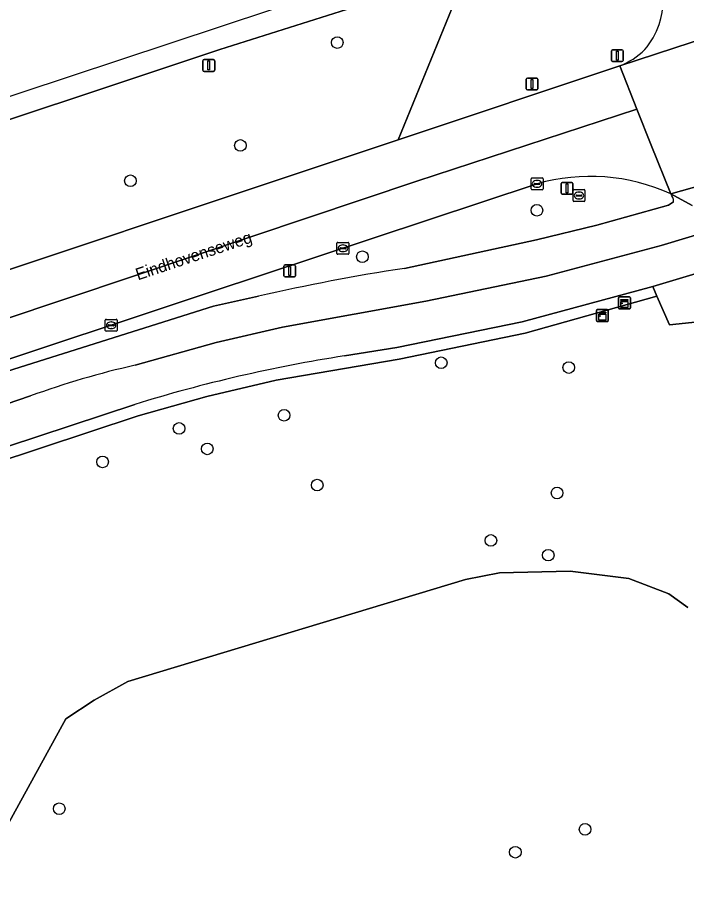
# Model space of a CAD drawing. Extents: x 162082 to 163401, y 388089 to 388636.
# Drawn here: x 162135.7 to 162191.9, y 388429.5 to 388502.7 of the extents above; entities that cross this region are included whole.
import ezdxf

# ---------------------------------------------------------------- set-up
doc = ezdxf.new("R2010")
doc.units = 0
for name, color, linetype in [('IMGEO_Berm_groen', 7, 'Continuous'), ('IMGEO_Boom', 7, 'Continuous'), ('IMGEO_Fietspad_gesloten', 7, 'Continuous'), ('IMGEO_Groenvoorziening', 7, 'Continuous'), ('IMGEO_Kast', 7, 'Continuous'), ('IMGEO_Kolk', 7, 'Continuous'), ('IMGEO_Lichtmast', 7, 'Continuous'), ('IMGEO_Loofbos', 7, 'Continuous'), ('IMGEO_Openbare_ruimte_label', 7, 'Continuous'), ('IMGEO_Rijbaan_regionaal_gesloten', 7, 'Continuous'), ('IMGEO_Rioolput', 7, 'Continuous'), ('IMGEO_Verkeersbordpaal', 7, 'Continuous'), ('IMGEO_Verkeersregelinstallatiepaal', 7, 'Continuous'), ('IMGEO_Voetpad_open', 7, 'Continuous')]:
    doc.layers.add(name, color=color, linetype=linetype)

msp = doc.modelspace()

# ---------------------------------------------------------------- linework, layer by layer
at = {"layer": 'IMGEO_Berm_groen'}
for points in [[(162182.913, 388509.596), (162173.435, 388506.586), (162172.94, 388505.371), (162168.161, 388493.65), (162167.664, 388492.43), (162186.253, 388498.633)], [(162179.321, 388488.723), (162151.79, 388479.601), (162130.844, 388472.616), (162126.677, 388471.258), (162126.927, 388470.499), (162126.415, 388470.328), (162152.169, 388478.453)], [(162145.551, 388470.202), (162124.066, 388463.101), (162124.127, 388462.752), (162115.246, 388459.072), (162115.132, 388459.761), (162115.076, 388460.073), (162114.525, 388463.169), (162114.5, 388463.309), (162113.845, 388466.99), (162112.598, 388473.997), (162112.45, 388474.83), (162112.381, 388475.216), (162110.598, 388485.039), (162110.577, 388485.155), (162110.422, 388486.009), (162110.1, 388487.783), (162106.061, 388486.443), (162106.271, 388485.258), (162104.283, 388484.864), (162104.113, 388485.797)], [(162168.184, 388481.623), (162179.283, 388484.025), (162184.324, 388485.241), (162190.345, 388486.937), (162190.774, 388487.218)], [(162220.353, 388411.769), (162198.713, 388479.081), (162197.9, 388480.945), (162196.87, 388482.458), (162189.034, 388480.096), (162189.38, 388479.302), (162190.438, 388476.87), (162194.958, 388477.348), (162199.885, 388462.478), (162209.231, 388435.377), (162217.14, 388410.656)], [(162129.502, 388463.844), (162145.851, 388469.248), (162151.603, 388470.876), (162157.431, 388472.224), (162167.732, 388473.998), (162178.317, 388476.172), (162189.38, 388479.302), (162189.034, 388480.096), (162178.08, 388477.144), (162167.552, 388474.982), (162163.164, 388474.276)], [(162152.169, 388478.453), (162155.945, 388479.29)]]:
    msp.add_lwpolyline(points, dxfattribs=at)
msp.add_lwpolyline([(162168.161, 388493.65), (162172.94, 388505.371), (162173.435, 388506.586), (162152.7, 388500), (162125.209, 388490.852), (162119.403, 388488.96), (162119.574, 388488.142), (162119.595, 388488.041), (162121.418, 388478.225), (162121.508, 388477.815), (162121.67, 388477.082), (162167.664, 388492.43)], close=True, dxfattribs=at)
for centre, radius, start, end in [((162183.61, 388504.121), 6.28, 341.22895, 18.96852), ((162183.477, 388504.169), 6.421, 319.51382, 341.2023), ((162184.088, 388504.281), 6.049, 290.97595, 314.94941), ((162183.786, 388473.192), 16.16, 65.31255, 106.03852), ((162189.743, 388487.215), 1.031, 0.17871, 39.8015), ((162193.777, 388314.091), 169.476, 98.68567, 102.89884), ((162182.258, 388351.619), 124.134, 98.84807, 107.1996)]:
    msp.add_arc(centre, radius, start, end, dxfattribs=at)
at = {"layer": 'IMGEO_Boom'}
for centre in [(162162.551, 388500.587), (162154.419, 388491.944), (162145.193, 388488.979), (162179.305, 388486.503), (162164.658, 388482.601), (162171.272, 388473.696), (162181.977, 388473.297), (162158.087, 388469.288), (162149.277, 388468.179), (162151.642, 388466.468), (162142.852, 388465.373), (162160.866, 388463.424), (162180.994, 388462.764), (162175.439, 388458.777), (162180.254, 388457.541), (162139.216, 388436.249), (162183.344, 388434.516), (162177.494, 388432.599)]:
    msp.add_circle(centre, 0.489, dxfattribs=at)
at = {"layer": 'IMGEO_Fietspad_gesloten'}
for points in [[(162192.329, 388486.909), (162190.535, 388487.875)], [(162190.774, 388487.218), (162190.345, 388486.937), (162184.324, 388485.241), (162179.283, 388484.025), (162168.184, 388481.623)], [(162169.99, 388478.857), (162180.07, 388480.967), (162189.741, 388483.554), (162194.648, 388485.031)], [(162155.945, 388479.29), (162152.169, 388478.453), (162126.415, 388470.328), (162125.474, 388470.031), (162122.99, 388469.247), (162123.493, 388466.375), (162123.631, 388466.422), (162136.803, 388470.914)], [(162145.584, 388473.491), (162152.396, 388475.404), (162157.94, 388476.675), (162169.99, 388478.857)]]:
    msp.add_lwpolyline(points, dxfattribs=at)
for centre, radius, start, end in [((162189.743, 388487.215), 1.031, 0.17871, 39.8015), ((162193.777, 388314.091), 169.476, 98.68567, 102.89884), ((162161.295, 388403.708), 71.529, 102.68796, 110.02328)]:
    msp.add_arc(centre, radius, start, end, dxfattribs=at)
at = {"layer": 'IMGEO_Groenvoorziening'}
msp.add_lwpolyline([(162191.968, 388453.155), (162190.366, 388454.283), (162187.024, 388455.572), (162182.083, 388456.211), (162176.166, 388456.047), (162173.323, 388455.508), (162144.984, 388446.93), (162142.155, 388445.363), (162139.758, 388443.795), (162134.886, 388434.881), (162134.756, 388429.774), (162130.402, 388429.182)], dxfattribs=at)
at = {"layer": 'IMGEO_Kast'}
for p, q in [((162186.15, 388478.297), (162186.15, 388479.138)), ((162186.15, 388479.138), (162186.15, 388478.297)), ((162186.225, 388479.222), (162187.066, 388479.222)), ((162187.066, 388479.222), (162186.225, 388479.222)), ((162187.15, 388479.147), (162187.15, 388478.306)), ((162187.15, 388478.306), (162187.15, 388479.147)), ((162187.075, 388478.222), (162186.234, 388478.222)), ((162186.234, 388478.222), (162187.075, 388478.222)), ((162184.297, 388477.235), (162184.297, 388478.076)), ((162184.297, 388478.076), (162184.297, 388477.235)), ((162184.372, 388478.16), (162185.213, 388478.16)), ((162185.213, 388478.16), (162184.372, 388478.16)), ((162185.297, 388478.085), (162185.297, 388477.244)), ((162185.297, 388477.244), (162185.297, 388478.085)), ((162185.222, 388477.16), (162184.381, 388477.16)), ((162184.381, 388477.16), (162185.222, 388477.16))]:
    msp.add_line(p, q, dxfattribs=at)
for points in [[(162186.345, 388479.012), (162186.945, 388479.012), (162186.945, 388478.927), (162186.345, 388478.927), (162186.345, 388479.012)], [(162186.345, 388478.837), (162186.945, 388478.837), (162186.945, 388478.348), (162186.345, 388478.348), (162186.345, 388478.837)], [(162184.492, 388477.95), (162185.092, 388477.95), (162185.092, 388477.865), (162184.492, 388477.865), (162184.492, 388477.95)], [(162184.492, 388477.775), (162185.092, 388477.775), (162185.092, 388477.286), (162184.492, 388477.286), (162184.492, 388477.775)]]:
    msp.add_lwpolyline(points, dxfattribs=at)
for centre in [(162186.429, 388478.686), (162184.576, 388477.624)]:
    msp.add_circle(centre, 0.0377, dxfattribs=at)
for centre, start, end in [((162186.228, 388479.144), 92.4484, 184.28452), ((162186.228, 388479.144), 92.4484, 184.28452), ((162187.072, 388479.144), 2.4484, 94.28452), ((162187.072, 388479.144), 2.4484, 94.28452), ((162186.228, 388478.3), 182.4484, 274.28452), ((162186.228, 388478.3), 182.4484, 274.28452), ((162187.072, 388478.3), 272.4484, 4.28452), ((162187.072, 388478.3), 272.4484, 4.28452), ((162184.375, 388478.082), 92.4484, 184.28452), ((162184.375, 388478.082), 92.4484, 184.28452), ((162185.219, 388478.082), 2.4484, 94.28452), ((162185.219, 388478.082), 2.4484, 94.28452), ((162184.375, 388477.238), 182.4484, 274.28452), ((162184.375, 388477.238), 182.4484, 274.28452), ((162185.219, 388477.238), 272.4484, 4.28452), ((162185.219, 388477.238), 272.4484, 4.28452)]:
    msp.add_arc(centre, 0.0779, start, end, dxfattribs=at)
at = {"layer": 'IMGEO_Kolk'}
for p, q in [((162178.892, 388489.221), (162179.744, 388489.221)), ((162178.817, 388488.295), (162178.817, 388489.147)), ((162179.076, 388488.715), (162179.076, 388488.727)), ((162179.514, 388488.678), (162179.116, 388488.678)), ((162179.119, 388488.764), (162179.517, 388488.764)), ((162179.328, 388488.441), (162179.303, 388488.441)), ((162179.305, 388489.001), (162179.33, 388489.001)), ((162179.56, 388488.727), (162179.56, 388488.715)), ((162179.818, 388489.147), (162179.818, 388488.295)), ((162179.744, 388488.221), (162178.892, 388488.221)), ((162162.524, 388482.883), (162162.524, 388483.735)), ((162162.599, 388483.809), (162163.451, 388483.809)), ((162162.783, 388483.303), (162162.783, 388483.315)), ((162162.826, 388483.352), (162163.224, 388483.352)), ((162163.012, 388483.589), (162163.037, 388483.589)), ((162163.267, 388483.315), (162163.267, 388483.303)), ((162163.525, 388483.735), (162163.525, 388482.883)), ((162163.451, 388482.809), (162162.599, 388482.809)), ((162163.221, 388483.266), (162162.823, 388483.266)), ((162163.035, 388483.029), (162163.01, 388483.029)), ((162143.078, 388476.419), (162143.078, 388477.271)), ((162143.153, 388477.345), (162144.005, 388477.345)), ((162143.337, 388476.839), (162143.337, 388476.851)), ((162143.775, 388476.802), (162143.377, 388476.802)), ((162143.38, 388476.888), (162143.778, 388476.888)), ((162143.566, 388477.125), (162143.591, 388477.125)), ((162143.821, 388476.851), (162143.821, 388476.839)), ((162144.079, 388477.271), (162144.079, 388476.419)), ((162144.005, 388476.345), (162143.153, 388476.345)), ((162143.589, 388476.565), (162143.564, 388476.565))]:
    msp.add_line(p, q, dxfattribs=at)
for points in [[(162178.892, 388489.221), (162179.744, 388489.221)], [(162178.817, 388488.295), (162178.817, 388489.147)], [(162179.818, 388489.147), (162179.818, 388488.295)], [(162179.744, 388488.221), (162178.892, 388488.221)], [(162162.524, 388482.883), (162162.524, 388483.735)], [(162162.599, 388483.809), (162163.451, 388483.809)], [(162163.525, 388483.735), (162163.525, 388482.883)], [(162163.451, 388482.809), (162162.599, 388482.809)], [(162143.078, 388476.419), (162143.078, 388477.271)], [(162143.153, 388477.345), (162144.005, 388477.345)], [(162144.079, 388477.271), (162144.079, 388476.419)], [(162144.005, 388476.345), (162143.153, 388476.345)]]:
    msp.add_lwpolyline(points, dxfattribs=at)
for centre, radius, start, end in [((162178.894, 388489.145), 0.0765, 91.55205, 178.44795), ((162178.894, 388489.145), 0.0765, 91.55205, 178.44795), ((162179.742, 388489.145), 0.0765, 1.55205, 88.44795), ((162179.742, 388489.145), 0.0765, 1.55205, 88.44795), ((162179.116, 388488.724), 0.0403, 85.87752, 175.75265), ((162179.113, 388488.714), 0.0366, 178.93798, 274.71019), ((162179.517, 388488.721), 0.043, 264.86636, 352.45326), ((162179.521, 388488.726), 0.0386, 1.73085, 96.63898), ((162178.894, 388488.297), 0.0765, 181.55205, 268.44795), ((162178.894, 388488.297), 0.0765, 181.55205, 268.44795), ((162179.742, 388488.297), 0.0765, 271.55205, 358.44795), ((162179.742, 388488.297), 0.0765, 271.55205, 358.44795), ((162162.601, 388483.733), 0.0765, 91.55205, 178.44795), ((162162.601, 388483.733), 0.0765, 91.55205, 178.44795), ((162162.823, 388483.312), 0.0403, 85.87752, 175.75265), ((162163.228, 388483.314), 0.0386, 1.73085, 96.63898), ((162163.449, 388483.733), 0.0765, 1.55205, 88.44795), ((162163.449, 388483.733), 0.0765, 1.55205, 88.44795), ((162162.601, 388482.885), 0.0765, 181.55205, 268.44795), ((162162.601, 388482.885), 0.0765, 181.55205, 268.44795), ((162162.82, 388483.302), 0.0366, 178.93798, 274.71019), ((162163.224, 388483.309), 0.043, 264.86636, 352.45326), ((162163.449, 388482.885), 0.0765, 271.55205, 358.44795), ((162163.449, 388482.885), 0.0765, 271.55205, 358.44795), ((162143.155, 388477.269), 0.0765, 91.55205, 178.44795), ((162143.155, 388477.269), 0.0765, 91.55205, 178.44795), ((162143.377, 388476.848), 0.0403, 85.87752, 175.75265), ((162143.374, 388476.838), 0.0366, 178.93798, 274.71019), ((162143.778, 388476.845), 0.043, 264.86636, 352.45326), ((162143.782, 388476.85), 0.0386, 1.73085, 96.63898), ((162144.003, 388477.269), 0.0765, 1.55205, 88.44795), ((162144.003, 388477.269), 0.0765, 1.55205, 88.44795), ((162143.155, 388476.421), 0.0765, 181.55205, 268.44795), ((162143.155, 388476.421), 0.0765, 181.55205, 268.44795), ((162144.003, 388476.421), 0.0765, 271.55205, 358.44795), ((162144.003, 388476.421), 0.0765, 271.55205, 358.44795)]:
    msp.add_arc(centre, radius, start, end, dxfattribs=at)
for centre, major_axis, ratio, start_param, end_param in [((162179.304, 388488.721), (-0.387, 0.002), 0.722429, 4.712389, 7.853982), ((162179.329, 388488.721), (-0.39, 0.002), 0.717154, 1.570796, 4.712389), ((162163.011, 388483.309), (-0.387, 0.002), 0.722429, 4.712389, 7.853982), ((162163.036, 388483.309), (-0.39, 0.002), 0.717154, 1.570796, 4.712389), ((162143.565, 388476.845), (-0.387, 0.002), 0.722429, 4.712389, 7.853982), ((162143.59, 388476.845), (-0.39, 0.002), 0.717154, 1.570796, 4.712389)]:
    msp.add_ellipse(centre, major_axis=major_axis, ratio=ratio, start_param=start_param, end_param=end_param, dxfattribs=at)
at = {"layer": 'IMGEO_Lichtmast'}
for p, q in [((162151.271, 388498.265), (162151.271, 388499.065)), ((162151.271, 388499.065), (162151.271, 388498.265)), ((162151.371, 388499.165), (162152.161, 388499.165)), ((162152.161, 388499.165), (162151.371, 388499.165)), ((162152.261, 388499.065), (162152.261, 388498.265)), ((162152.261, 388498.265), (162152.261, 388499.065)), ((162152.161, 388498.165), (162151.371, 388498.165)), ((162151.371, 388498.165), (162152.161, 388498.165)), ((162158.167, 388481.908), (162158.957, 388481.908)), ((162158.957, 388481.908), (162158.167, 388481.908)), ((162158.067, 388481.008), (162158.067, 388481.808)), ((162158.067, 388481.808), (162158.067, 388481.008)), ((162159.057, 388481.808), (162159.057, 388481.008)), ((162159.057, 388481.008), (162159.057, 388481.808)), ((162158.957, 388480.908), (162158.167, 388480.908)), ((162158.167, 388480.908), (162158.957, 388480.908))]:
    msp.add_line(p, q, dxfattribs=at)
for points in [[(162151.691, 388499.04), (162151.841, 388499.04), (162151.841, 388498.29), (162151.691, 388498.29), (162151.691, 388499.04)], [(162158.487, 388481.783), (162158.637, 388481.783), (162158.637, 388481.033), (162158.487, 388481.033), (162158.487, 388481.783)]]:
    msp.add_lwpolyline(points, dxfattribs=at)
for centre, start, end in [((162151.371, 388499.065), 90, 180), ((162151.371, 388499.065), 90, 180), ((162152.161, 388499.065), 0, 90), ((162152.161, 388499.065), 360, 90), ((162151.371, 388498.265), 180, 270), ((162151.371, 388498.265), 180, 270), ((162152.161, 388498.265), 270, 0), ((162152.161, 388498.265), 270, 0), ((162158.167, 388481.808), 90, 180), ((162158.167, 388481.808), 90, 180), ((162158.957, 388481.808), 0, 90), ((162158.957, 388481.808), 360, 90), ((162158.167, 388481.008), 180, 270), ((162158.167, 388481.008), 180, 270), ((162158.957, 388481.008), 270, 0), ((162158.957, 388481.008), 270, 0)]:
    msp.add_arc(centre, 0.1, start, end, dxfattribs=at)
at = {"layer": 'IMGEO_Loofbos'}
for points in [[(162194.958, 388477.348), (162190.438, 388476.87), (162189.38, 388479.302), (162178.317, 388476.172), (162167.732, 388473.998), (162157.431, 388472.224), (162151.603, 388470.876), (162145.851, 388469.248), (162129.502, 388463.844), (162125.422, 388462.129), (162107.623, 388456.211), (162108.165, 388452.708), (162108.896, 388453.004), (162110.356, 388448.348), (162113.525, 388440.157), (162116.259, 388434.035), (162118.41, 388433.409)], [(162130.402, 388429.182), (162134.756, 388429.774), (162134.886, 388434.881), (162139.758, 388443.795), (162142.155, 388445.363), (162144.984, 388446.93), (162173.323, 388455.508), (162176.166, 388456.047), (162182.083, 388456.211), (162187.024, 388455.572), (162190.366, 388454.283), (162191.968, 388453.155)]]:
    msp.add_lwpolyline(points, dxfattribs=at)
at = {"layer": 'IMGEO_Rijbaan_regionaal_gesloten'}
for points in [[(162182.21, 388511.702), (162119.076, 388490.761), (162119.403, 388488.96), (162125.209, 388490.852), (162152.7, 388500), (162173.435, 388506.586), (162182.913, 388509.596)], [(162187.699, 388495.001), (162186.253, 388498.633), (162167.664, 388492.43), (162121.67, 388477.082), (162122.305, 388473.295), (162134.256, 388477.225), (162150.87, 388482.8), (162169.229, 388488.96)]]:
    msp.add_lwpolyline(points, close=True, dxfattribs=at)
for points in [[(162211.794, 388499.348), (162217.557, 388501.321), (162221.111, 388502.504), (162218.53, 388509.288), (162218.255, 388509.195), (162215.415, 388508.212), (162214.914, 388508.048), (162186.253, 388498.633), (162187.699, 388495.001), (162188.9, 388491.982), (162190.535, 388487.875), (162200.396, 388490.649)], [(162186.253, 388498.633), (162214.914, 388508.048)], [(162190.535, 388487.875), (162188.9, 388491.982), (162187.699, 388495.001), (162169.229, 388488.96), (162150.87, 388482.8), (162134.256, 388477.225), (162122.305, 388473.295), (162122.856, 388470.013), (162126.677, 388471.258), (162130.844, 388472.616), (162151.79, 388479.601), (162179.321, 388488.723)], [(162200.396, 388490.649), (162190.535, 388487.875), (162192.329, 388486.909)]]:
    msp.add_lwpolyline(points, dxfattribs=at)
for centre, radius, start, end in [((162183.61, 388504.121), 6.28, 341.22895, 18.96852), ((162183.477, 388504.169), 6.421, 319.51382, 341.2023), ((162184.088, 388504.281), 6.049, 290.97595, 314.94941), ((162183.786, 388473.192), 16.16, 65.31255, 106.03852)]:
    msp.add_arc(centre, radius, start, end, dxfattribs=at)
at = {"layer": 'IMGEO_Rioolput'}
for p, q in [((162182.338, 388487.316), (162182.338, 388488.168)), ((162182.413, 388488.242), (162183.265, 388488.242)), ((162182.597, 388487.736), (162182.597, 388487.748)), ((162182.64, 388487.785), (162183.038, 388487.785)), ((162182.826, 388488.022), (162182.851, 388488.022)), ((162183.081, 388487.748), (162183.081, 388487.736)), ((162183.339, 388488.168), (162183.339, 388487.316)), ((162183.265, 388487.242), (162182.413, 388487.242)), ((162183.035, 388487.699), (162182.637, 388487.699)), ((162182.849, 388487.462), (162182.824, 388487.462))]:
    msp.add_line(p, q, dxfattribs=at)
for points in [[(162182.338, 388487.316), (162182.338, 388488.168)], [(162182.413, 388488.242), (162183.265, 388488.242)], [(162183.339, 388488.168), (162183.339, 388487.316)], [(162183.265, 388487.242), (162182.413, 388487.242)]]:
    msp.add_lwpolyline(points, dxfattribs=at)
for centre, radius, start, end in [((162182.415, 388488.166), 0.0765, 91.55205, 178.44795), ((162182.415, 388488.166), 0.0765, 91.55205, 178.44795), ((162182.637, 388487.745), 0.0403, 85.87752, 175.75265), ((162182.634, 388487.735), 0.0366, 178.93798, 274.71019), ((162183.038, 388487.742), 0.043, 264.86636, 352.45326), ((162183.042, 388487.747), 0.0386, 1.73085, 96.63898), ((162183.263, 388488.166), 0.0765, 1.55205, 88.44795), ((162183.263, 388488.166), 0.0765, 1.55205, 88.44795), ((162182.415, 388487.318), 0.0765, 181.55205, 268.44795), ((162182.415, 388487.318), 0.0765, 181.55205, 268.44795), ((162183.263, 388487.318), 0.0765, 271.55205, 358.44795), ((162183.263, 388487.318), 0.0765, 271.55205, 358.44795)]:
    msp.add_arc(centre, radius, start, end, dxfattribs=at)
for centre, major_axis, ratio, start_param, end_param in [((162182.825, 388487.742), (-0.387, 0.002), 0.722429, 4.712389, 7.853982), ((162182.85, 388487.742), (-0.39, 0.002), 0.717154, 1.570796, 4.712389)]:
    msp.add_ellipse(centre, major_axis=major_axis, ratio=ratio, start_param=start_param, end_param=end_param, dxfattribs=at)
at = {"layer": 'IMGEO_Verkeersbordpaal'}
for p, q in [((162185.552, 388499.088), (162185.552, 388499.888)), ((162185.552, 388499.888), (162185.552, 388499.088)), ((162185.652, 388499.988), (162186.442, 388499.988)), ((162186.442, 388499.988), (162185.652, 388499.988)), ((162186.542, 388499.888), (162186.542, 388499.088)), ((162186.542, 388499.088), (162186.542, 388499.888)), ((162186.442, 388498.988), (162185.652, 388498.988)), ((162185.652, 388498.988), (162186.442, 388498.988))]:
    msp.add_line(p, q, dxfattribs=at)
msp.add_lwpolyline([(162185.972, 388499.863), (162186.122, 388499.863), (162186.122, 388499.113), (162185.972, 388499.113), (162185.972, 388499.863)], dxfattribs=at)
for centre, start, end in [((162185.652, 388499.888), 90, 180), ((162185.652, 388499.888), 90, 180), ((162186.442, 388499.888), 0, 90), ((162186.442, 388499.888), 360, 90), ((162185.652, 388499.088), 180, 270), ((162185.652, 388499.088), 180, 270), ((162186.442, 388499.088), 270, 0), ((162186.442, 388499.088), 270, 0)]:
    msp.add_arc(centre, 0.1, start, end, dxfattribs=at)
at = {"layer": 'IMGEO_Verkeersregelinstallatiepaal'}
for p, q in [((162178.402, 388496.709), (162178.402, 388497.509)), ((162178.402, 388497.509), (162178.402, 388496.709)), ((162178.502, 388497.609), (162179.292, 388497.609)), ((162179.292, 388497.609), (162178.502, 388497.609)), ((162179.392, 388497.509), (162179.392, 388496.709)), ((162179.392, 388496.709), (162179.392, 388497.509)), ((162179.292, 388496.609), (162178.502, 388496.609)), ((162178.502, 388496.609), (162179.292, 388496.609)), ((162181.333, 388487.945), (162181.333, 388488.745)), ((162181.333, 388488.745), (162181.333, 388487.945)), ((162181.433, 388488.845), (162182.223, 388488.845)), ((162182.223, 388488.845), (162181.433, 388488.845)), ((162182.323, 388488.745), (162182.323, 388487.945)), ((162182.323, 388487.945), (162182.323, 388488.745)), ((162182.223, 388487.845), (162181.433, 388487.845)), ((162181.433, 388487.845), (162182.223, 388487.845))]:
    msp.add_line(p, q, dxfattribs=at)
for points in [[(162178.822, 388497.484), (162178.972, 388497.484), (162178.972, 388496.734), (162178.822, 388496.734), (162178.822, 388497.484)], [(162181.753, 388488.72), (162181.903, 388488.72), (162181.903, 388487.97), (162181.753, 388487.97), (162181.753, 388488.72)]]:
    msp.add_lwpolyline(points, dxfattribs=at)
for centre, start, end in [((162178.502, 388497.509), 90, 180), ((162178.502, 388497.509), 90, 180), ((162179.292, 388497.509), 0, 90), ((162179.292, 388497.509), 360, 90), ((162178.502, 388496.709), 180, 270), ((162178.502, 388496.709), 180, 270), ((162179.292, 388496.709), 270, 0), ((162179.292, 388496.709), 270, 0), ((162181.433, 388488.745), 90, 180), ((162181.433, 388488.745), 90, 180), ((162182.223, 388488.745), 0, 90), ((162182.223, 388488.745), 360, 90), ((162181.433, 388487.945), 180, 270), ((162181.433, 388487.945), 180, 270), ((162182.223, 388487.945), 270, 0), ((162182.223, 388487.945), 270, 0)]:
    msp.add_arc(centre, 0.1, start, end, dxfattribs=at)
at = {"layer": 'IMGEO_Voetpad_open'}
for points in [[(162194.648, 388485.031), (162189.741, 388483.554), (162180.07, 388480.967), (162169.99, 388478.857), (162157.94, 388476.675), (162152.396, 388475.404), (162145.584, 388473.491)], [(162178.08, 388477.144), (162189.034, 388480.096), (162196.87, 388482.458)], [(162163.164, 388474.276), (162167.552, 388474.982), (162178.08, 388477.144)], [(162136.803, 388470.914), (162123.631, 388466.422), (162123.493, 388466.375), (162123.52, 388466.22), (162124.066, 388463.101), (162145.551, 388470.202)]]:
    msp.add_lwpolyline(points, dxfattribs=at)
for centre, radius, start, end in [((162182.258, 388351.619), 124.134, 98.84807, 107.1996), ((162161.295, 388403.708), 71.529, 102.68796, 110.02328)]:
    msp.add_arc(centre, radius, start, end, dxfattribs=at)

# ---------------------------------------------------------------- texts
at = {"layer": 'IMGEO_Openbare_ruimte_label'}
msp.add_text('Eindhovenseweg', height=1, rotation=18.36247, dxfattribs=at).set_placement((162145.82, 388480.611))

doc.saveas('drawing.dxf')
